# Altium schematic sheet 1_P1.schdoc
size 309 x 223 mm; Symbol: Sheet-Symbol_A4; Device: Sheet-Symbol_A4; @Page Name: P1; @Create Date: 2023-08-18; @Page Count: 1; @Page No: 1; @Project Name: 【废土科技】带抬头显示及监控器的多功能观测仪_V2; @Schematic Name: 综合传感器板; @Update Date: 2023-08-18; Company: 嘉立创EDA; Drawed: Kevin_Wuu; Page Size: A4; Version: V1.0
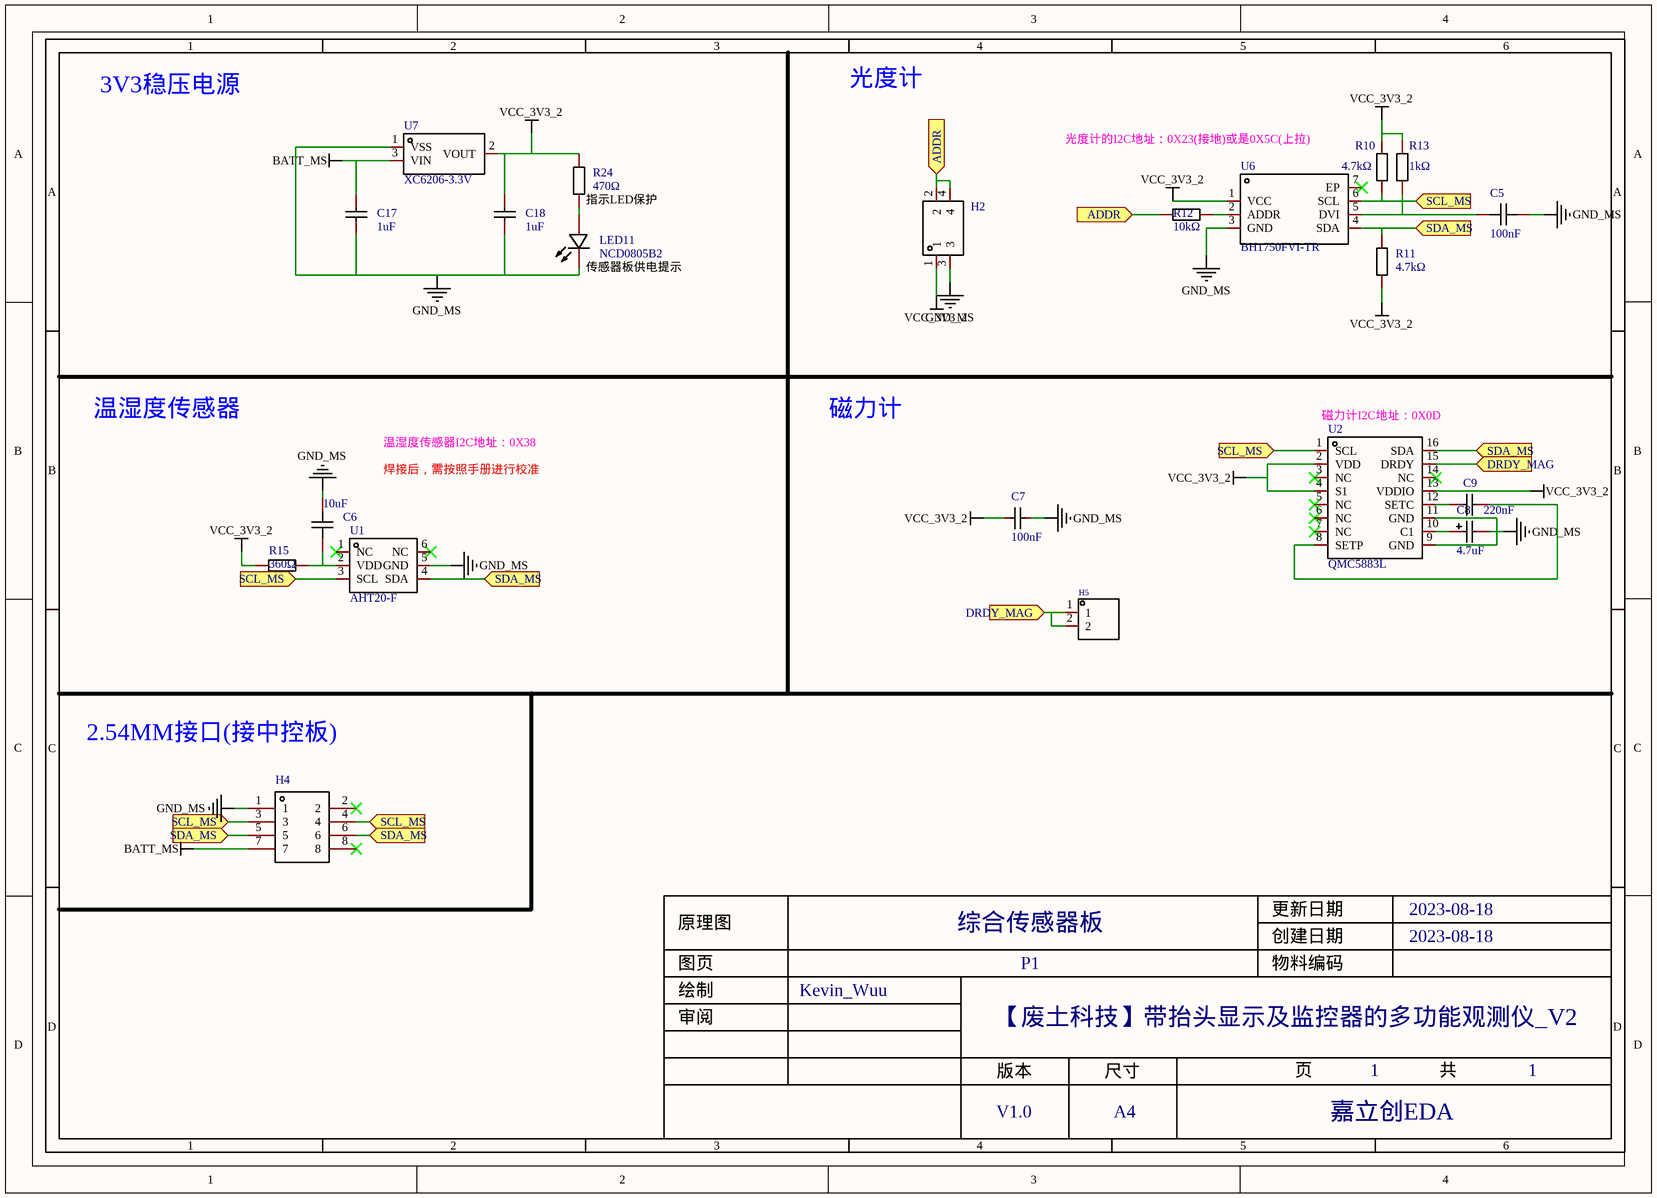
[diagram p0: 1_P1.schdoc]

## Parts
C5  100nF  [C0603]
C6  10uF  [C0805]
C7  100nF  [C1206]
C8  4.7uF  [CASE-A_3216]
C9  220nF  [C0603]
C17  1uF  [C0805]
C18  1uF  [C0805]
H2  HDR-M_2.54_2x2  [HDR-TH_4P-P2.54-V-M-R2-C2-S2.54-1]  (value not drawn)
H4  HDR-M_2.54_2x4  [HDR-TH_8P-P2.54-V-M-R2-C4-S2.54]  (value not drawn)
H5  HDR-M_2.54_1x2P  [HDR-TH_2P-P2.54-V-M-1]  (value not drawn)
LED11  NCD0805B2  [LED0805-R-RD]
R10  4.7kΩ  [R0805]
R11  4.7kΩ  [R0805]
R12  10kΩ  [R0805]
R13  1kΩ  [R0805]
R15  360Ω  [R0603]
R24  470Ω  [R0603]
U1  AHT20-F  [SENSOR-SMD-6_AHT20]
U2  QMC5883L  [LGA-16_L3.0-W3.0-P0.50-BL_SQ]
U6  BH1750FVI-TR  [WSOF-6_L2.6-W1.6-P0.50-TL-EP]
U7  XC6206-3.3V  [SSOT-3_L2.9-W1.6-P0.95-LS2.8-BR]

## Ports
ADDR (in), DRDY_MAG (in), SCL_MS (in), SDA_MS (in)

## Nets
BATT_MS: C17.1 H4.7 U7.3(VIN)
GND_MS: C5.2 C6.2 C7.2 C8.2 C17.2 C18.2 H2.3 H4.1 LED11.2(-) U1.5(GND) U2.9(GND) U2.11(GND) U6.3(GND) U7.1(VSS)
VCC_3V3_2: C7.1 C18.1 H2.1 R10.2 R11.1 R13.2 R15.1 R24.2 U2.2(VDD) U2.4(S1) U2.13(VDDIO) U6.1(VCC) U7.2(VOUT)
ADDR: H2.2 H2.4 R12.2 ; port ADDR
DRDY_MAG: H5.1 H5.2 U2.15(DRDY) ; port DRDY_MAG
SCL_MS: H4.3 H4.4 R10.1 U1.3(SCL) U2.1(SCL) U6.6(SCL) ; port SCL_MS
SDA_MS: H4.5 H4.6 R11.2 U1.4(SDA) U2.16(SDA) U6.4(SDA) ; port SDA_MS
NetC5_1: C5.1 R13.1 U6.5(DVI)
NetC6_1: C6.1 R15.2 U1.2(VDD)
NetC8_1: C8.1 U2.10(C1)
NetC9_1: C9.1 U2.12(SETC)
NetC9_2: C9.2 U2.8(SETP)
NetLED11_1: LED11.1(+) R24.1
NetR12_1: R12.1 U6.2(ADDR)

Not connected (* = marked no-connect by the designer): H4 2* 8*; U1 1(NC)* 6(NC)*; U2 3(NC)* 5(NC)* 6(NC)* 7(NC)* 14(NC)*; U6 7(EP)*

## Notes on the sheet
- 3V3稳压电源
- 光度计
- (near U6) 光度计的I2C地址：0X23(接地)或是0X5C(上拉)
- (near R24) 指示LED保护
- (near LED11) 传感器板供电提示
- 温湿度传感器
- 温湿度传感器I2C地址：0X38
- 焊接后，需按照手册进行校准
- 磁力计
- (near U2) 磁力计I2C地址：0X0D
- 2.54MM接口(接中控板)

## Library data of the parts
C5 = CC0603KRX7R9BB104: 容值:100nF;精度:±10%;额定电压:50V;材质(温度系数):X7R;; Manufacturer: YAGEO(国巨); Add into BOM: yes; Tolerance: ±10%; Voltage Rated: 50V; Temperature Coefficient: X7R
C6 = GRM21BR61H106KE43L: 容值:10uF;精度:±10%;额定电压:50V;材质(温度系数):X5R;; Manufacturer: muRata(村田); Add into BOM: yes; Tolerance: ±10%; Voltage Rated: 50V; Temperature Coefficient: X5R
C7 = 1206B104K500AT: 容值:100nF;精度:±10%;额定电压:50V;材质(温度系数):X7R;; Manufacturer: FH(风华); Add into BOM: yes; Tolerance: ±10%; Voltage Rated: 50V; Temperature Coefficient: X7R
C8 = TAJA475K016RNJ: 容值:4.7uF;精度:±10%;额定电压:16V;等效串联电阻:4Ω@100kHz;工作温度:-55℃~+125℃;; Manufacturer: Kyocera AVX; Add into BOM: yes; Tolerance: ±10%; Rated Voltage: 16V
C9 = CL10B224KA8NNNC: 容值:220nF;精度:±10%;额定电压:25V;材质(温度系数):X7R;; Manufacturer: SAMSUNG(三星); Add into BOM: yes; Tolerance: ±10%; Voltage Rated: 25V; Temperature Coefficient: X7R
C17 C18 = CL21B105KBFNNNE: 容值:1uF;精度:±10%;额定电压:50V;材质(温度系数):X7R;; Manufacturer: SAMSUNG(三星); Add into BOM: yes; Tolerance: ±10%; Voltage Rated: 50V; Temperature Coefficient: X7R
H2 = HDR-M_2.54_2x2: Symbol: HDR-M-2.54_2x2; Convert to PCB: yes; Check: false
H4 = HDR-M_2.54_2x4: Symbol: HDR-M-2.54_2x4; Convert to PCB: yes; Check: false
H5 = HDR-M_2.54_1x2P: Manufacturer: Ckmtw(灿科盟); Manufacturer Part: B-2100S02P-A110; Symbol: 210S-1*2P L=11.6MMGold-plated black; Convert to PCB: yes
LED11 = NCD0805B2: 发光颜色:蓝灯;; Manufacturer: 国星光电; Symbol: FC-A2012BK-470H2; Add into BOM: yes; Emitted Color: 蓝灯
R10 R11 = 0805W8F4701T5E: 电阻类型:厚膜电阻;阻值:4.7kΩ;精度:±1%;功率:125mW;; Manufacturer: UNI-ROYAL(厚声); Add into BOM: yes; Tolerance: ±1%; Power(Watts): 125mW; Temperature Coefficient: ±100ppm/℃; Overload Voltage (Max): 150V
R12 = RMCF0805FT10K0: 电阻类型:厚膜电阻;阻值:10kΩ;精度:±1%;功率:125mW;; Manufacturer: SEI(Stackpole Electronics Inc.); Add into BOM: yes; Tolerance: ±1%; Power(Watts): 125mW; Temperature Coefficient: ±100ppm/℃; Overload Voltage (Max): 150V
R13 = 0805W8F1001T5E: 电阻类型:厚膜电阻;阻值:1kΩ;精度:±1%;功率:125mW;; Manufacturer: UNI-ROYAL(厚声); Add into BOM: yes; Tolerance: ±1%; Power(Watts): 125mW; Temperature Coefficient: ±100ppm/℃; Overload Voltage (Max): 150V
R15 = 0603WAF3600T5E: 电阻类型:厚膜电阻;阻值:360Ω;精度:±1%;功率:100mW;; Manufacturer: UNI-ROYAL(厚声); Add into BOM: yes; Tolerance: ±1%; Power(Watts): 100mW; Temperature Coefficient: ±100ppm/℃; Overload Voltage (Max): 75V
R24 = 0603WAF4700T5E: 电阻类型:厚膜电阻;阻值:470Ω;精度:±1%;功率:100mW;; Manufacturer: UNI-ROYAL(厚声); Add into BOM: yes; Tolerance: ±1%; Power(Watts): 100mW; Temperature Coefficient: ±100ppm/℃; Overload Voltage (Max): 75V
U1 = AHT20-F: Manufacturer: 广州奥松; Add into BOM: yes
U2 = QMC5883L: Manufacturer: QST(上海矽睿); Add into BOM: yes
U6 = BH1750FVI-TR: 数字16-bit I2C串行输出，环境光传感器，工作电压：2.4V~3.6V; Manufacturer: ROHM(罗姆); Add into BOM: yes
U7 = XC6206-3.3V: 输出类型:固定;输出极性:正;最大输入电压:6V;输出电压:3.3V;输出电流:250mA;; Manufacturer: YONGYUTAI(永裕泰); Add into BOM: yes; Output Type: 固定; Output Polarity: 正; Number of Outputs: 1; Maximum Input Voltage: 6V; Output Voltage: 3.3V; Output Current: 250mA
